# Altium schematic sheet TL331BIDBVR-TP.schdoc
size 127 x 101 mm
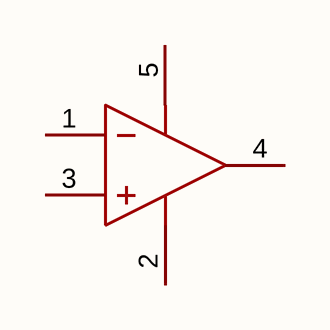
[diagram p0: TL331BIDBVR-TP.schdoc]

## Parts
U?  tl331bidbvr-tp  [SOT-23-5_L2.9-W1.6-P0.95-LS2.8-BL]  (value not drawn)

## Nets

Not connected (* = marked no-connect by the designer): U? 1(IN-) 2(GND) 3(IN+) 4(OUT) 5(VCC)

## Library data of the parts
U? = tl331bidbvr-tp: 比较器数:1;输入失调电压(Vos):2mV;输入偏置电流(Ib):25nA;; Manufacturer: TECH PUBLIC(台舟); AddInBom: yes; ModelId: 018c57e721114987ae90467fe9f1d259; ModelTransform: 114.96,110.236,0,0,0,0,0,0,0; Number of Channels: 1; Vos - Input Offset Voltage: 2mV; Ib - Input Bias Current: 25nA; Output Mode: CMOS；ECL；MOS；DTL；TTL; Quiescent Current: 400uA; Single Supply: 2V~36V; Dual Supply: -18V~-1V；1V~18V; Input Offset Current(Ios): 50nA; Response Time (tr): 1.3us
